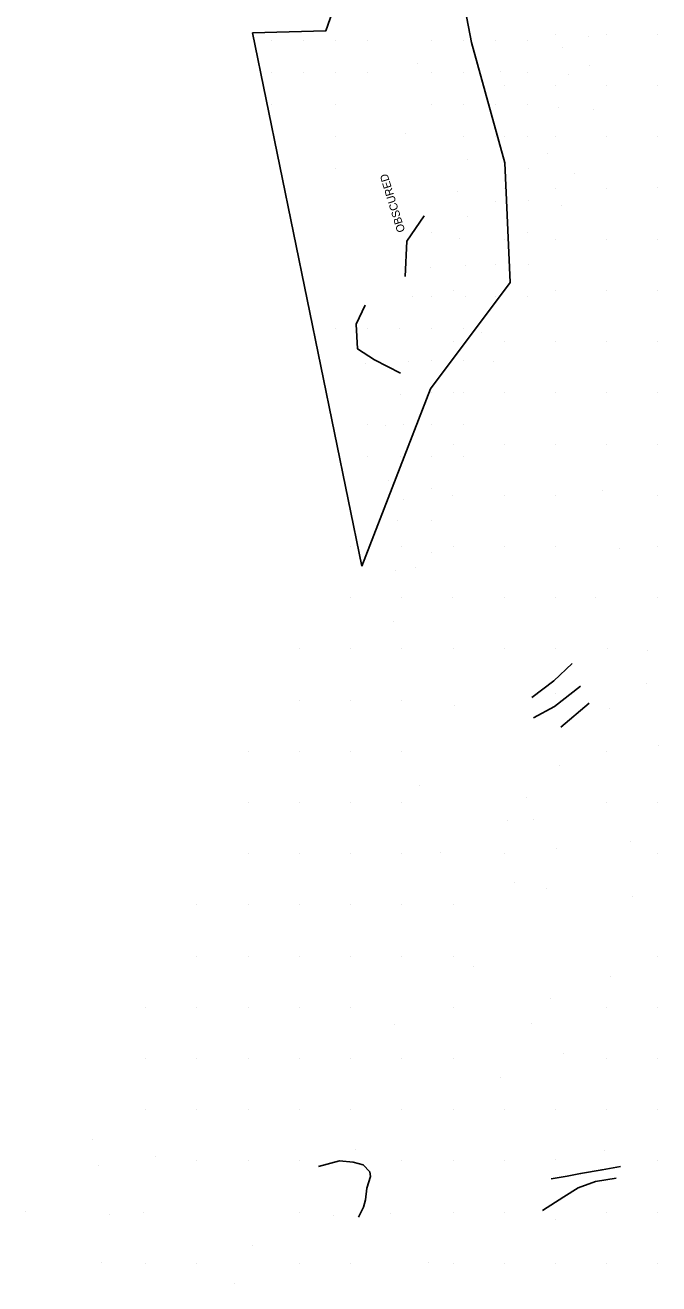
# Model space of a CAD drawing. Extents: x 524772 to 528246, y 273285 to 283088.
# Drawn here: x 527169.5 to 527290.2, y 274521.4 to 274761.2 of the extents above; entities that cross this region are included whole.
import ezdxf

# ---------------------------------------------------------------- set-up
doc = ezdxf.new("R2010")
doc.units = 0
for name, color, linetype in [('PH Exist DTM Breakline', 7, 'Continuous'), ('PH Exist DTM Obscure Area', 7, 'Continuous'), ('PH Exist DTM Obscure Area Text', 7, 'Continuous'), ('PH Exist DTM Point', 7, 'Continuous')]:
    doc.layers.add(name, color=color, linetype=linetype)

msp = doc.modelspace()

# ---------------------------------------------------------------- linework, layer by layer
at = {"layer": 'PH Exist DTM Breakline'}
for points in [[(527241.86, 274713.31), (527242.18, 274719.99), (527245.47, 274724.82)], [(527240.99, 274694.88), (527236.02, 274697.4), (527232.79, 274699.48), (527232.51, 274704.19), (527234.25, 274707.8)], [(527273.68, 274639.57), (527270.2, 274636.24), (527265.96, 274633.08)], [(527266.32, 274629.19), (527270.32, 274631.35), (527275.24, 274635.25)], [(527271.51, 274627.43), (527276.93, 274631.99)], [(527232.97, 274534.08), (527233.91, 274535.98), (527234.32, 274537.4), (527234.56, 274539.62), (527235.24, 274541.84), (527235.14, 274542.71), (527233.83, 274544.04), (527231.93, 274544.55), (527229.35, 274544.81), (527225.33, 274543.75)], [(527282.89, 274543.73), (527279.36, 274543.13), (527275.28, 274542.38), (527272.7, 274541.92), (527269.64, 274541.4)], [(527268.01, 274535.37), (527272.11, 274537.97), (527274.8, 274539.71), (527278.1, 274540.86), (527282.07, 274541.51)]]:
    msp.add_lwpolyline(points, dxfattribs=at)
at = {"layer": 'PH Exist DTM Obscure Area'}
for points in [[(527212.79, 274759.72), (527226.75, 274760.09), (527232.6, 274776.81), (527242.75, 274782.11), (527250.77, 274777.4), (527254.52, 274757.86), (527260.85, 274734.96), (527261.85, 274712.14), (527246.67, 274691.89), (527233.61, 274658.08)], [(527212.79, 274759.72), (527233.61, 274658.08)]]:
    msp.add_lwpolyline(points, dxfattribs=at)
at = {"layer": 'PH Exist DTM Point'}
for p, q in [((527216.39, 274758.17), (527216.39, 274758.17)), ((527222.5, 274758.17), (527222.5, 274758.17)), ((527228.6, 274758.17), (527228.6, 274758.17)), ((527234.69, 274758.17), (527234.69, 274758.17)), ((527246.88, 274758.17), (527246.88, 274758.17)), ((527252.98, 274758.17), (527252.98, 274758.17)), ((527259.08, 274758.17), (527259.08, 274758.17)), ((527265.17, 274758.17), (527265.17, 274758.17)), ((527270.48, 274759.4), (527270.48, 274759.4)), ((527276.87, 274758.92), (527276.87, 274758.92)), ((527280.23, 274759.4), (527280.23, 274759.4)), ((527289.98, 274759.4), (527289.98, 274759.4)), ((527271.81, 274756.83), (527271.81, 274756.83)), ((527244.16, 274753.94), (527244.16, 274753.94)), ((527276.94, 274753.43), (527276.94, 274753.43)), ((527216.4, 274752.07), (527216.4, 274752.07)), ((527222.5, 274752.07), (527222.5, 274752.07)), ((527228.6, 274752.07), (527228.6, 274752.07)), ((527234.69, 274752.07), (527234.69, 274752.07)), ((527246.88, 274752.07), (527246.88, 274752.07)), ((527252.98, 274752.07), (527252.98, 274752.07)), ((527259.98, 274752.35), (527259.98, 274752.35)), ((527265.17, 274752.07), (527265.17, 274752.07)), ((527273.06, 274751.71), (527273.06, 274751.71)), ((527260.72, 274749.64), (527260.72, 274749.64)), ((527270.48, 274749.64), (527270.48, 274749.64)), ((527280.23, 274749.64), (527280.23, 274749.64)), ((527289.98, 274749.64), (527289.98, 274749.64)), ((527216.42, 274745.98), (527216.42, 274745.98)), ((527228.61, 274745.98), (527228.61, 274745.98)), ((527246.88, 274745.98), (527246.88, 274745.98)), ((527252.98, 274745.98), (527252.98, 274745.98)), ((527259.08, 274745.98), (527259.08, 274745.98)), ((527265.17, 274745.98), (527265.17, 274745.98)), ((527271.05, 274745.48), (527271.05, 274745.48)), ((527277.7, 274745.09), (527277.7, 274745.09)), ((527241.86, 274740.59), (527241.86, 274740.59)), ((527228.58, 274739.88), (527228.58, 274739.88)), ((527252.98, 274739.88), (527252.98, 274739.88)), ((527259.08, 274739.89), (527259.08, 274739.89)), ((527260.72, 274739.89), (527260.72, 274739.89)), ((527265.17, 274739.88), (527265.17, 274739.88)), ((527270.48, 274739.89), (527270.48, 274739.89)), ((527280.23, 274739.89), (527280.23, 274739.89)), ((527289.98, 274739.89), (527289.98, 274739.89)), ((527269, 274736.68), (527269, 274736.68)), ((527228.6, 274733.79), (527228.6, 274733.79)), ((527253.82, 274735.65), (527253.82, 274735.65)), ((527265.27, 274733.83), (527265.27, 274733.83)), ((527274.06, 274732.92), (527274.06, 274732.92)), ((527251.78, 274729.52), (527251.78, 274729.52)), ((527260.72, 274730.13), (527260.72, 274730.13)), ((527270.48, 274730.13), (527270.48, 274730.13)), ((527280.23, 274730.13), (527280.23, 274730.13)), ((527290, 274730.16), (527290, 274730.16)), ((527259.09, 274727.65), (527259.09, 274727.65)), ((527265.33, 274727.74), (527265.33, 274727.74)), ((527271.55, 274726.84), (527271.55, 274726.84)), ((527253.78, 274724.78), (527253.78, 274724.78)), ((527246.89, 274721.58), (527246.89, 274721.58)), ((527265.17, 274721.59), (527265.17, 274721.59)), ((527252.26, 274720.53), (527252.26, 274720.53)), ((527260.72, 274720.38), (527260.72, 274720.38)), ((527270.48, 274720.38), (527270.48, 274720.38)), ((527280.23, 274720.38), (527280.23, 274720.38)), ((527289.98, 274720.38), (527289.98, 274720.38)), ((527246.59, 274715.03), (527246.59, 274715.03)), ((527253.42, 274715.3), (527253.42, 274715.3)), ((527259.08, 274715.5), (527259.08, 274715.5)), ((527265.38, 274715.56), (527265.38, 274715.56)), ((527243.21, 274709.57), (527243.21, 274709.57)), ((527246.88, 274709.4), (527246.88, 274709.4)), ((527250.97, 274710.63), (527250.97, 274710.63)), ((527253.33, 274709.51), (527253.33, 274709.51)), ((527259.07, 274709.4), (527259.07, 274709.4)), ((527260.72, 274710.63), (527260.72, 274710.63)), ((527265.17, 274709.4), (527265.17, 274709.4)), ((527270.48, 274710.63), (527270.48, 274710.63)), ((527280.23, 274710.63), (527280.23, 274710.63)), ((527290.01, 274710.61), (527290.01, 274710.61)), ((527228.6, 274703.31), (527228.6, 274703.31)), ((527234.69, 274703.31), (527234.69, 274703.31)), ((527240.86, 274703.32), (527240.86, 274703.32)), ((527246.88, 274703.31), (527246.88, 274703.31)), ((527252.97, 274703.32), (527252.97, 274703.32)), ((527256.49, 274702.67), (527256.49, 274702.67)), ((527250.97, 274700.87), (527250.97, 274700.87)), ((527260.73, 274700.86), (527260.73, 274700.86)), ((527270.48, 274700.87), (527270.48, 274700.87)), ((527280.23, 274700.87), (527280.23, 274700.87)), ((527289.98, 274700.87), (527289.98, 274700.87)), ((527234.23, 274696.74), (527234.23, 274696.74)), ((527242.54, 274697.07), (527242.54, 274697.07)), ((527246.88, 274697.21), (527246.88, 274697.21)), ((527252.98, 274697.21), (527252.98, 274697.21)), ((527258.64, 274697.08), (527258.64, 274697.08)), ((527240.96, 274690.86), (527240.96, 274690.86)), ((527246.88, 274691.11), (527246.88, 274691.11)), ((527250.97, 274691.12), (527250.97, 274691.12)), ((527252.98, 274691.11), (527252.98, 274691.11)), ((527260.72, 274691.12), (527260.72, 274691.12)), ((527270.48, 274691.12), (527270.48, 274691.12)), ((527280.21, 274691.13), (527280.21, 274691.13)), ((527289.98, 274691.12), (527289.98, 274691.12)), ((527234.69, 274685.02), (527234.69, 274685.02)), ((527238.06, 274684.93), (527238.06, 274684.93)), ((527241.52, 274685.13), (527241.52, 274685.13)), ((527246.88, 274685.02), (527246.88, 274685.02)), ((527252.98, 274685.02), (527252.98, 274685.02)), ((527250.97, 274681.37), (527250.97, 274681.37)), ((527260.72, 274681.37), (527260.72, 274681.37)), ((527270.48, 274681.37), (527270.48, 274681.37)), ((527280.23, 274681.37), (527280.23, 274681.37)), ((527289.98, 274681.37), (527289.98, 274681.37)), ((527234.69, 274678.92), (527234.69, 274678.92)), ((527240.88, 274678.96), (527240.88, 274678.96)), ((527246.88, 274678.92), (527246.88, 274678.92)), ((527252.98, 274678.92), (527252.98, 274678.92)), ((527238.6, 274674.46), (527238.6, 274674.46)), ((527246.88, 274672.84), (527246.88, 274672.84)), ((527250.94, 274671.63), (527250.94, 274671.63)), ((527260.72, 274671.61), (527260.72, 274671.61)), ((527270.48, 274671.61), (527270.48, 274671.61)), ((527279.37, 274672.49), (527279.37, 274672.49)), ((527289.98, 274671.61), (527289.98, 274671.61)), ((527241.52, 274670.9), (527241.52, 274670.9)), ((527240.43, 274666.77), (527240.43, 274666.77)), ((527246.88, 274666.73), (527246.88, 274666.73)), ((527231.46, 274661.86), (527231.46, 274661.86)), ((527241.23, 274661.87), (527241.23, 274661.87)), ((527250.97, 274661.86), (527250.97, 274661.86)), ((527260.72, 274661.86), (527260.72, 274661.86)), ((527270.48, 274661.86), (527270.48, 274661.86)), ((527282.76, 274661.41), (527282.76, 274661.41)), ((527289.98, 274661.86), (527289.98, 274661.86)), ((527246.88, 274660.63), (527246.88, 274660.63)), ((527239.95, 274657.28), (527239.95, 274657.28)), ((527243.74, 274657.89), (527243.74, 274657.89)), ((527231.46, 274652.11), (527231.46, 274652.11)), ((527241.22, 274652.11), (527241.22, 274652.11)), ((527250.94, 274652.12), (527250.94, 274652.12)), ((527260.72, 274652.11), (527260.72, 274652.11)), ((527270.48, 274652.11), (527270.48, 274652.11)), ((527278.18, 274652.06), (527278.18, 274652.06)), ((527289.98, 274652.11), (527289.98, 274652.11)), ((527239.61, 274647.58), (527239.61, 274647.58)), ((527221.69, 274642.35), (527221.69, 274642.35)), ((527231.46, 274642.35), (527231.46, 274642.35)), ((527241.22, 274642.35), (527241.22, 274642.35)), ((527250.98, 274642.33), (527250.98, 274642.33)), ((527260.72, 274642.35), (527260.72, 274642.35)), ((527270.47, 274642.37), (527270.47, 274642.37)), ((527280.31, 274642.36), (527280.31, 274642.36)), ((527288.03, 274641.99), (527288.03, 274641.99)), ((527287.81, 274635.82), (527287.81, 274635.82)), ((527270.58, 274633.83), (527270.58, 274633.83)), ((527221.71, 274632.6), (527221.71, 274632.6)), ((527231.46, 274632.6), (527231.46, 274632.6)), ((527241.22, 274632.6), (527241.22, 274632.6)), ((527251.25, 274631.55), (527251.25, 274631.55)), ((527280.71, 274630.95), (527280.71, 274630.95)), ((527290.17, 274623.91), (527290.17, 274623.91)), ((527211.96, 274622.85), (527211.96, 274622.85)), ((527221.71, 274622.85), (527221.71, 274622.85)), ((527231.46, 274622.85), (527231.46, 274622.85)), ((527241.22, 274622.85), (527241.22, 274622.85)), ((527280.23, 274622.85), (527280.23, 274622.85)), ((527271.32, 274620.15), (527271.32, 274620.15)), ((527244.53, 274616.33), (527244.53, 274616.33)), ((527265.06, 274613.95), (527265.06, 274613.95)), ((527211.96, 274613.09), (527211.96, 274613.09)), ((527221.71, 274613.09), (527221.71, 274613.09)), ((527231.46, 274613.09), (527231.46, 274613.09)), ((527241.2, 274613.09), (527241.2, 274613.09)), ((527280.23, 274613.09), (527280.23, 274613.09)), ((527289.97, 274613.09), (527289.97, 274613.09)), ((527261.26, 274609.62), (527261.26, 274609.62)), ((527266.33, 274609.85), (527266.33, 274609.85)), ((527270.73, 274604.26), (527270.73, 274604.26)), ((527284.82, 274605.6), (527284.82, 274605.6)), ((527211.96, 274603.34), (527211.96, 274603.34)), ((527221.73, 274603.34), (527221.73, 274603.34)), ((527231.46, 274603.34), (527231.46, 274603.34)), ((527241.22, 274603.34), (527241.22, 274603.34)), ((527248.59, 274603.56), (527248.59, 274603.56)), ((527260.7, 274603.35), (527260.7, 274603.35)), ((527289.86, 274603.4), (527289.86, 274603.4)), ((527262.62, 274597.86), (527262.62, 274597.86)), ((527268.85, 274596.76), (527268.85, 274596.76)), ((527285.1, 274595.27), (527285.1, 274595.27)), ((527202.2, 274593.58), (527202.2, 274593.58)), ((527211.96, 274593.58), (527211.96, 274593.58)), ((527221.71, 274593.58), (527221.71, 274593.58)), ((527231.46, 274593.58), (527231.46, 274593.58)), ((527241.22, 274593.58), (527241.22, 274593.58)), ((527250.97, 274593.58), (527250.97, 274593.58)), ((527202.2, 274583.83), (527202.2, 274583.83)), ((527211.96, 274583.83), (527211.96, 274583.83)), ((527221.71, 274583.83), (527221.71, 274583.83)), ((527231.46, 274583.83), (527231.46, 274583.83)), ((527241.22, 274583.83), (527241.22, 274583.83)), ((527250.97, 274583.83), (527250.97, 274583.83)), ((527289.98, 274583.83), (527289.98, 274583.83)), ((527254.85, 274581.92), (527254.85, 274581.92)), ((527281.05, 274579.97), (527281.05, 274579.97)), ((527269.51, 274575.76), (527269.51, 274575.76)), ((527192.45, 274574.08), (527192.45, 274574.08)), ((527202.2, 274574.08), (527202.2, 274574.08)), ((527211.96, 274574.08), (527211.96, 274574.08)), ((527221.71, 274574.08), (527221.71, 274574.08)), ((527231.46, 274574.08), (527231.46, 274574.08)), ((527250.97, 274574.08), (527250.97, 274574.08)), ((527280.22, 274574.1), (527280.22, 274574.1)), ((527289.98, 274574.08), (527289.98, 274574.08)), ((527239.85, 274570.77), (527239.85, 274570.77)), ((527265.87, 274571.06), (527265.87, 274571.06)), ((527192.45, 274564.32), (527192.45, 274564.32)), ((527202.2, 274564.32), (527202.2, 274564.32)), ((527211.96, 274564.32), (527211.96, 274564.32)), ((527221.71, 274564.32), (527221.71, 274564.32)), ((527231.46, 274564.32), (527231.46, 274564.32)), ((527241.22, 274564.32), (527241.22, 274564.32)), ((527250.97, 274564.32), (527250.97, 274564.32)), ((527271.95, 274565.25), (527271.95, 274565.25)), ((527280.24, 274564.3), (527280.24, 274564.3)), ((527289.98, 274564.32), (527289.98, 274564.32)), ((527260.03, 274560.71), (527260.03, 274560.71)), ((527192.43, 274554.55), (527192.43, 274554.55)), ((527202.2, 274554.57), (527202.2, 274554.57)), ((527211.96, 274554.57), (527211.96, 274554.57)), ((527221.71, 274554.57), (527221.71, 274554.57)), ((527231.46, 274554.57), (527231.46, 274554.57)), ((527241.22, 274554.57), (527241.22, 274554.57)), ((527250.97, 274554.57), (527250.97, 274554.57)), ((527260.72, 274554.57), (527260.72, 274554.57)), ((527270.48, 274554.57), (527270.48, 274554.57)), ((527280.23, 274554.57), (527280.23, 274554.57)), ((527289.98, 274554.57), (527289.98, 274554.57)), ((527182.24, 274548.87), (527182.24, 274548.87)), ((527232.46, 274546.89), (527232.46, 274546.89)), ((527279.84, 274546.7), (527279.84, 274546.7)), ((527183.44, 274543.93), (527183.44, 274543.93)), ((527194.25, 274545.59), (527194.25, 274545.59)), ((527202.2, 274544.82), (527202.2, 274544.82)), ((527212.04, 274544.8), (527212.04, 274544.8)), ((527221.71, 274544.82), (527221.71, 274544.82)), ((527241.22, 274544.82), (527241.22, 274544.82)), ((527250.97, 274544.82), (527250.97, 274544.82)), ((527260.72, 274544.82), (527260.72, 274544.82)), ((527270.44, 274545.07), (527270.44, 274545.07)), ((527289.98, 274544.82), (527289.98, 274544.82)), ((527169.47, 274535.2), (527169.47, 274535.2)), ((527185.55, 274534.55), (527185.55, 274534.55)), ((527191.93, 274534.93), (527191.93, 274534.93)), ((527221.71, 274535.06), (527221.71, 274535.06)), ((527228.18, 274534.37), (527228.18, 274534.37)), ((527239.08, 274534.76), (527239.08, 274534.76)), ((527250.97, 274535.06), (527250.97, 274535.06)), ((527260.72, 274535.06), (527260.72, 274535.06)), ((527280.22, 274535.04), (527280.22, 274535.04)), ((527289.98, 274535.06), (527289.98, 274535.06)), ((527270.55, 274533.66), (527270.55, 274533.66)), ((527212.73, 274528.66), (527212.73, 274528.66)), ((527184.09, 274525.44), (527184.09, 274525.44)), ((527192.45, 274525.31), (527192.45, 274525.31)), ((527202.2, 274525.31), (527202.2, 274525.31)), ((527221.71, 274525.31), (527221.71, 274525.31)), ((527231.46, 274525.31), (527231.46, 274525.31)), ((527246.23, 274525.39), (527246.23, 274525.39)), ((527250.97, 274525.31), (527250.97, 274525.31)), ((527260.72, 274525.31), (527260.72, 274525.31)), ((527270.48, 274525.31), (527270.48, 274525.31)), ((527280.23, 274525.31), (527280.23, 274525.31)), ((527289.98, 274525.31), (527289.98, 274525.31)), ((527209.44, 274521.39), (527209.44, 274521.39))]:
    msp.add_line(p, q, dxfattribs=at)

# ---------------------------------------------------------------- texts
at = {"layer": 'PH Exist DTM Obscure Area Text'}
msp.add_text('OBSCURED', height=1.524, rotation=107.1924, dxfattribs=at).set_placement((527241.87, 274721.96))

doc.saveas('drawing.dxf')
